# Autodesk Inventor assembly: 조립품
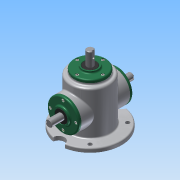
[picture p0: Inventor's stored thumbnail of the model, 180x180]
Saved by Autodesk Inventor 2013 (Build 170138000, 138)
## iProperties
Created: 2018-04
Part Number: 조립품
Document SubType Name: Assembly
Designer: Administrator
Author: Administrator
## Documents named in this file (16)
- C:\Users\Administrator\Desktop\480408V1008\조립품.iam
- C:\Users\Administrator\Desktop\480408V1008\본체.ipt
- C:\Users\Administrator\Desktop\480408V1008\베어링 6203.ipt
- C:\Users\Administrator\Desktop\480408V1008\볼트 M4.ipt
- 볼트 M4.ipt
- C:\Users\Administrator\Desktop\480408V1008\서브 베벨기어.ipt
- C:\Users\Administrator\Desktop\480408V1008\서브 축.ipt
- 서브 축.ipt
- C:\Users\Administrator\Desktop\480408V1008\오일 실.ipt
- 오일 실.ipt
- C:\Users\Administrator\Desktop\480408V1008\커버.ipt
- C:\Users\Administrator\Desktop\480408V1008\키 4x4.ipt
- C:\Users\Administrator\Desktop\480408V1008\메인 축.ipt
- 메인 축.ipt
- C:\Users\Administrator\Desktop\480408V1008\키 5x5.ipt
- C:\Users\Administrator\Desktop\480408V1008\메인 베벨기어.ipt
